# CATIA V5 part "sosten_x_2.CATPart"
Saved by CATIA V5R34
Part number: Part3
Bounding box of the stored display mesh (mm): x -22 to 13, y -30 to 30, z -13 to 38
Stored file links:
  C:\Users\Apolinar\Desktop\cnc\sosten_x_2.CATPart
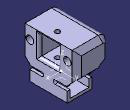
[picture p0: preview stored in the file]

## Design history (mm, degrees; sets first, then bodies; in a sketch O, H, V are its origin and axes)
AxisSystem1: origin (0, 0, 0), X (1, 0, 0), Y (0, 1, 0), Z (0, 0, 1)
Body1 (main body)
  Sketch1 on ZX plane of AxisSystem1, origin (0, 0, 0), H (0, 0, 1), V (1, 0, 0)
    line L1 (10, 10) -> (10, -10)
    line L2 (10, -10) -> (-10, -10)
    line L3 (-10, -10) -> (-10, 10)
    line L4 (-10, 10) -> (10, 10)
    line L5 (13, 13) -> (13, -13)
    line L6 (13, -13) -> (-13, -13)
    line L7 (-13, -13) -> (-13, 13)
    line L8 (-13, 13) -> (13, 13)
    length L1 = 20
    length L4 = 20
    distance L5 L1 = 3
    distance L2 L6 = 3
    vertical: L1 V, L3 V, L5 V, L7 V
    horizontal: L2 H, L4 H, L6 H, L8 H
    equidistance: L1 L3 O, L2 L4 O, L5 L7 O, L6 L8 O
  Pad1: profile Sketch1, direction (0, 1, 0), length 20, mirrored extent
  Sketch2 on face of Pad1 from Sketch1.L6, origin (-13, 0, 0), H (0, -1, 0), V (0, 0, 1)
    construction line L1 (-7, 0) -> (-20, 0)
    point P1 (-7, 0)
    point P2 (-20, 0)
    line L2 (-7, -2) -> (-20, -2)
    line L3 (-20, 2) -> (-7, 2)
    arc A1 centre (-20, 0) radius 2 from (-20, -2) to (-20, 2) cw
    arc A2 centre (-7, 0) radius 2 from (-7, 2) to (-7, -2) cw
    point P3 (-7, -2)
    point P4 (-20, -2)
    point P5 (-20, 2)
    point P6 (-7, 2)
    reference projected line E1 (-20, -13) -> (-20, 13) from edge [face of Pad1 from Sketch1.L6 | end face of Pad1]
    construction line L4 (7, 0) -> (20, 0)
    point P9 (7, -2)
    point P10 (20, -2)
    point P11 (20, 2)
    point P12 (7, 2)
    line L5 (7, -2) -> (20, -2)
    line L6 (20, 2) -> (7, 2)
    arc A3 centre (20, 0) radius 2 from (20, -2) to (20, 2) ccw
    arc A4 centre (7, 0) radius 2 from (7, 2) to (7, -2) ccw
    distance L1 L2 = 2
    distance A2 A4 = 10
    coincidence: P1 H, P2 E1
    horizontal: L1 H
    tangency: A1 L2, A2 L2, A1 L3, A2 L3
    symmetry: L1 L4 V, P3 P9 V, P4 P10 V, P5 P11 V, P6 P12 V, L2 L5 V, L3 L6 V, A1 A3 V, A2 A4 V
  Pocket1: profile Sketch2, direction (1, 0, 0), through (limit type 3)
  Sketch3 on face of Pad1 from Sketch1.L5, origin (0, 0, 13), H (1, 0, 0), V (0, 1, 0)
    point P1 (-4.5, 0)
    line L1 (13, 30) -> (13, -30)
    line L2 (13, -30) -> (-22, -30)
    line L3 (-22, -30) -> (-22, 30)
    line L4 (-22, 30) -> (13, 30)
    reference projected line E1 (13, -20) -> (13, 20) from edge [face of Pad1 from Sketch1.L8 | face of Pad1 from Sketch1.L5]
    length L1 = 60
    length L2 = 35
    coincidence: P1 H, L1 E1
    vertical: L1 V, L3 V
    horizontal: L2 H, L4 H
    equidistance: L1 L3 P1, L2 L4 P1
  Pad2: profile Sketch3, direction (0, 0, 1), length 25
  Sketch4 on face of Pad2, origin (13, 0, 0), H (0, 1, 0), V (0, 0, 1)
    circle A1 centre (-20, 25.5) radius 4
    point P1 (-20, 25.5)
    circle A2 centre (20, 25.5) radius 4
    reference projected line E1 (-30, 38) -> (30, 38) from edge [face of Pad2 from Sketch3.L1 | end face of Pad2]
    reference projected line E2 (-30, 13) -> (-30, 38) from edge [face of Pad2 from Sketch3.L1 | face of Pad2 from Sketch3.L2]
    radius A1 = 4
    distance P1 E1 = 12.5
    distance P1 E2 = 10
    symmetry: A1 A2 V
  Pocket2: profile Sketch4, direction (-1, 0, 0), through (limit type 6)
  Sketch5 on face of Pad2, origin (13, 0, 0), H (0, 1, 0), V (0, 0, 1)
    point P1 (0, 24)
    line L1 (10, 34) -> (10, 14)
    line L2 (10, 14) -> (-10, 14)
    line L3 (-10, 14) -> (-10, 34)
    line L4 (-10, 34) -> (10, 34)
    reference projected line E1 (-30, 13) -> (30, 13) from edge [start face of Pad2 | face of Pad2]
    length L1 = 20
    length L4 = 20
    distance P1 E1 = 11
    coincidence: P1 V
    vertical: L1 V, L3 V
    horizontal: L2 H, L4 H
    equidistance: L1 L3 P1, L2 L4 P1
  Pocket3: profile Sketch5, direction (-1, 0, 0), length 25
  Sketch6 on end face of Pad2, origin (0, 0, 38), H (1, 0, 0), V (0, 1, 0)
    circle A1 centre (3.5, 0) radius 2.5
    point P1 (3.5, 0)
    reference projected line E1 (13, -30) -> (13, 30) from edge [face of Pad2 from Sketch3.L1 | end face of Pad2]
    radius A1 = 2.5
    distance P1 E1 = 9.5
    coincidence: P1 H
  Pocket4: profile Sketch6, direction (0, 0, -1), length 30
  Chamfer1: length 10, angle 45, on edge [start face of Pad1 | start face of Pad2]; edge [start face of Pad2 | end face of Pad1]
  Fillet1: radius 7, on edge [face of Pad1 from Sketch1.L6 | start face of Pad2]; edge [start face of Pad2 | face of Pad2 from Sketch3.L3]; edge [face of Pad2 from Sketch3.L3 | end face of Pad2]
  Chamfer2: length 5, angle 45, on edge [face of Pad2 from Sketch3.L4 | face of Fillet1] (x2); edge [face of Pad2 from Sketch3.L3 | face of Pad2 from Sketch3.L4]; edge [face of Pad2 from Sketch3.L4 | end face of Pad2]; edge [face of Pad2 from Sketch3.L4 | face of Pad2]; edge [face of Pad2 from Sketch3.L2 | face of Pad2 from Sketch3.L3]; edge [face of Pad2 from Sketch3.L2 | face of Fillet1] (x2); edge [face of Pad2 from Sketch3.L2 | end face of Pad2]; edge [face of Pad2 | face of Pad2 from Sketch3.L2]
  Fillet2: radius 3, on edge [face of Pad2 | face of Pocket3 from Sketch5.L1]; edge [face of Pad2 | face of Pocket3 from Sketch5.L4]; edge [face of Pad2 | face of Pocket3 from Sketch5.L3]; edge [face of Pad2 | face of Pocket3 from Sketch5.L2]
